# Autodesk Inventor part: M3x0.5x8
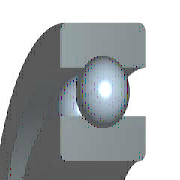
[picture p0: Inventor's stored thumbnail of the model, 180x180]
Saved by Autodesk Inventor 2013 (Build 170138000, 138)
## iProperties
Created: 2009-02
Part Number: M3x0.5x8
Material: 강, 연강
Description: 깊은 그루브 볼 베어링
Document SubType Name: Modeling
Standard: KS B 2023
Designer: KYOUNG IL JANG
Standards Organization: KS
Language: ko-KR
Size Designation: 6202 - 15 x 35 x 11
Categories: <MemberInstance><Categories><Category DisplayName="샤프트 부품" InternalName="7f7aeb1f-a693-4053-b835-cee3144e0d98" Mnemonic="SHFT"><Category DisplayName="베어링" Inter
Density: 7.86 g/cm^3
Mass: 45.8724 g
Surface Area: 51.5584 cm^2
Volume: 5.83618 cm^3
Vendor: CBT Solutions
Company: 한국ATC센터
IsCustomPart: 1
Author: KYOUNG IL JANG
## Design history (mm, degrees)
sketch "스케치" dims "d0" = 5.2 (= -0.26 x WD + 0.26 x BD)
  geometry: L1 (2.9, 12.5)-(8.1, 12.5); L2 (5.5, 12.5)-(5.5, 9.9); L3 (5.5, 12.5)-(5.5, 15.1); L4 (3.568, 10.76)-(0, 10.76); L5 (0, 7.5)-(11, 7.5); L6 (3.568, 14.24)-(0, 14.24); L7 (0, 17.5)-(11, 17.5); L8 (11, 7.5)-(11, 10.76); L9 (7.432, 10.76)-(11, 10.76); L10 (7.432, 14.24)-(11, 14.24); L11 (11, 17.5)-(11, 14.24); L12 (-1.4, 0)-(8.4, 0) reference; L13 (0, -0.3)-(0, 5.3) reference
  constraints: 22 end point, 4 point on line, 2 collinear, 2 perpendicular, 2 symmetric about line, 1 midpoint, 1 parallel, 14 other
  dimensions: "d9" = 15 diameter of L5 L12 (= WD); "d11" = 35 diameter of L7 L12 (= BD); "d12" = 11 distance between parallel lines of L8 L13 (= KB); "d13" = 21.52 diameter of L9 L12 (= 0.326 x BD + 0.674 x WD)
revolve "본체" stored, may be unused: angle "d6" = 90 deg
revolve "볼" stored, may be unused: angle "d7" = 90 deg
pattern_circular "IDS_ARRAYBALL[SIMPL:T]" dims angle "d3" = 360 deg
body "Solid1"
fillet "모깎기1" dims "d1" = 0.6 (= KRS)
other parameters: "WD" = 15 [user parameter; used in 5 equation terms], "BD" = 35 [user parameter; used in 5 equation terms], "KB" = 11 [user parameter; used in 1 equation term], "KRS" = 0.6 [user parameter; used in 1 equation term], "d4" = 0, "d5" = 0, "d8" = 0, "d14" = 0, "d15" = 0, "BBA" = 0 [user parameter], "BC0" = 3750000 [user parameter], "BC" = 7800000 [user parameter], "BR" = 17.5 (= 0.5 x BD) [user parameter], "WR" = 7.5 (= 0.5 x WD) [user parameter]
